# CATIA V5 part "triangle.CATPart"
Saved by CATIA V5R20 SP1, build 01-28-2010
Part number: triangle
Bounding box of the stored display mesh (mm): x 100 to 200, y -50 to 1050, z -269.927 to 749.927
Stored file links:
  C:\Users\Nicolas\Documents\Ifma\2A\S3\iao\projet\triangle.CATPart
  C:\Users\Nicolas\Documents\Ifma\2A\S3\iao\projet\Product1.CATProduct
  C:\Users\Nicolas\Documents\Ifma\2A\S3\iao\projet\bielle1.CATPart
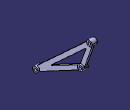
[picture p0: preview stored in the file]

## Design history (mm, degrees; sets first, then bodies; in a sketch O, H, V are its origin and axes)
Set1
  Plane1: linked copy from another document
  Line1 to Line3: linked copy from another document
  Plane2: linked copy from another document
  Plane3: linked copy from another document
  Point1 to Point3: linked copy from another document
Body1 (main body)
  Sketch1 on Plane1, origin (150, 0, 0), H (0, 1, 0), V (0, 0, 1)
    arc A1 centre (1000, 700) radius 50 from (1024.3076, 656.3063) to (950.2717, 705.2059) ccw
    point P1 (1000, 700)
    arc A2 centre (830, 220) radius 50 from (818.3442, 171.3776) to (876.3895, 238.6552) ccw
    point P2 (830, 220)
    arc A3 centre (0, -220) radius 50 from (-1.051, -170.011) to (46.7841, -237.6422) ccw
    point P3 (0, -220)
    reference projected point E1 (0, -220) from Line1
    reference projected point E2 (830, 220) from Line2
    reference projected point E3 (1000, 700) from Line3
    line L1 (46.7841, -237.6422) -> (818.3442, 171.3776)
    line L2 (783.2159, 237.6422) -> (239.5594, -50.5612)
    line L3 (805.6924, 263.6937) -> (914.2211, 570.1275)
    point P7 (805.6924, 263.6937)
    line L4 (876.3895, 238.6552) -> (1024.3076, 656.3063)
    line L5 (-1.051, -170.011) -> (950.2717, 705.2059)
    construction line L6 (0, -220) -> (830, 220)
    construction line L7 (830, 220) -> (1000, 700)
    construction line L8 (1000, 700) -> (0, -220)
    arc A4 centre (830, 220) radius 50 from (805.6924, 263.6937) to (783.2159, 237.6422) ccw
    line L9 (914.2211, 570.1275) -> (239.5594, -50.5612)
    radius A1 = 50
    radius A2 = 50
    radius A3 = 50
    distance L1 L2 = 75
    distance L4 L3 = 75
    distance L5 L9 = 75
    coincidence: P3 E1, P2 E2, P1 E3, P7 A2, A2 A4
    parallelism: L4 L3, L3 L7
    symmetry: L1 L2 L6, L4 L3 L7, L5 L9 L8
  Pad1: profile Sketch1, direction (1, 0, 0), length 20, mirrored extent
  Sketch2 on Plane1, origin (150, 0, 0), H (0, 1, 0), V (0, 0, 1)
    circle A1 centre (0, -220) radius 50
    circle A2 centre (830, 220) radius 50
    circle A3 centre (1000, 700) radius 50
    reference projected arc E1 centre (1000, 700) radius 50 from (1021.8954, 655.049) to (950.0981, 703.1311) ccw from edge [face of Pad1 from Sketch1.A1 | end face of Pad1]
    reference projected arc E2 centre (830, 220) radius 50 from (818.466, 171.3485) to (877.3353, 236.1048) ccw from edge [face of Pad1 from Sketch1.A2 | end face of Pad1]
    reference projected arc E3 centre (0, -220) radius 50 from (-3.1311, -170.0981) to (46.8281, -237.525) ccw from edge [face of Pad1 from Sketch1.A3 | end face of Pad1]
    coincidence: A3 E1, A2 E2, A1 E3
  Pad2: profile Sketch2, direction (1, 0, 0), up to Plane2, opposite side up to Plane3
  Sketch3 on start face of Pad2, origin (200, 1000, 700), H (0, 1, 0), V (0, 0, 1)
    point P1 (0, 0)
    reference projected point E1 (0, 0) from Point1
    coincidence: E1 P1
  Hole1: placed by Sketch3, at (200, 1000, 700) direction (-1, 0, 0), diameter 50, through (limit type 3)
  Sketch4 on start face of Pad2, origin (200, 750, 100), H (0, 1, 0), V (0, 0, 1)
    point P1 (80, 120)
    reference projected point E1 (80, 120) from Point2
    coincidence: E1 P1
  Hole2: placed by Sketch4, at (200, 830, 220) direction (-1, 0, 0), diameter 50, through (limit type 3)
  Sketch5 on start face of Pad2, origin (200, 0, -300), H (0, 1, 0), V (0, 0, 1)
    point P1 (0, 80)
    reference projected point E1 (0, 80) from Point3
    coincidence: E1 P1
  Hole3: placed by Sketch5, at (200, 0, -220) direction (-1, 0, 0), diameter 50, through (limit type 3)
  Fillet1: radius 5, on edge [face of Pad1 from Sketch1.L9 | face of Pad1 from Sketch1.L2]; edge [face of Pad1 from Sketch1.L2 | face of Pad2 from Sketch2.A2]; edge [face of Pad2 from Sketch2.A2 | face of Pad1 from Sketch1.L3]; edge [face of Pad1 from Sketch1.L3 | face of Pad1 from Sketch1.L9]; edge [face of Pad1 from Sketch1.L5 | face of Pad2 from Sketch2.A3]; edge [face of Pad2 from Sketch2.A3 | face of Pad1 from Sketch1.L4]; edge [face of Pad2 from Sketch2.A2 | face of Pad1 from Sketch1.L1]; edge [face of Pad1 from Sketch1.L4 | face of Pad2 from Sketch2.A2]; edge [face of Pad1 from Sketch1.L1 | face of Pad2 from Sketch2.A1]; edge [face of Pad2 from Sketch2.A1 | face of Pad1 from Sketch1.L5]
